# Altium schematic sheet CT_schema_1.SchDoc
size 526 x 485 mm
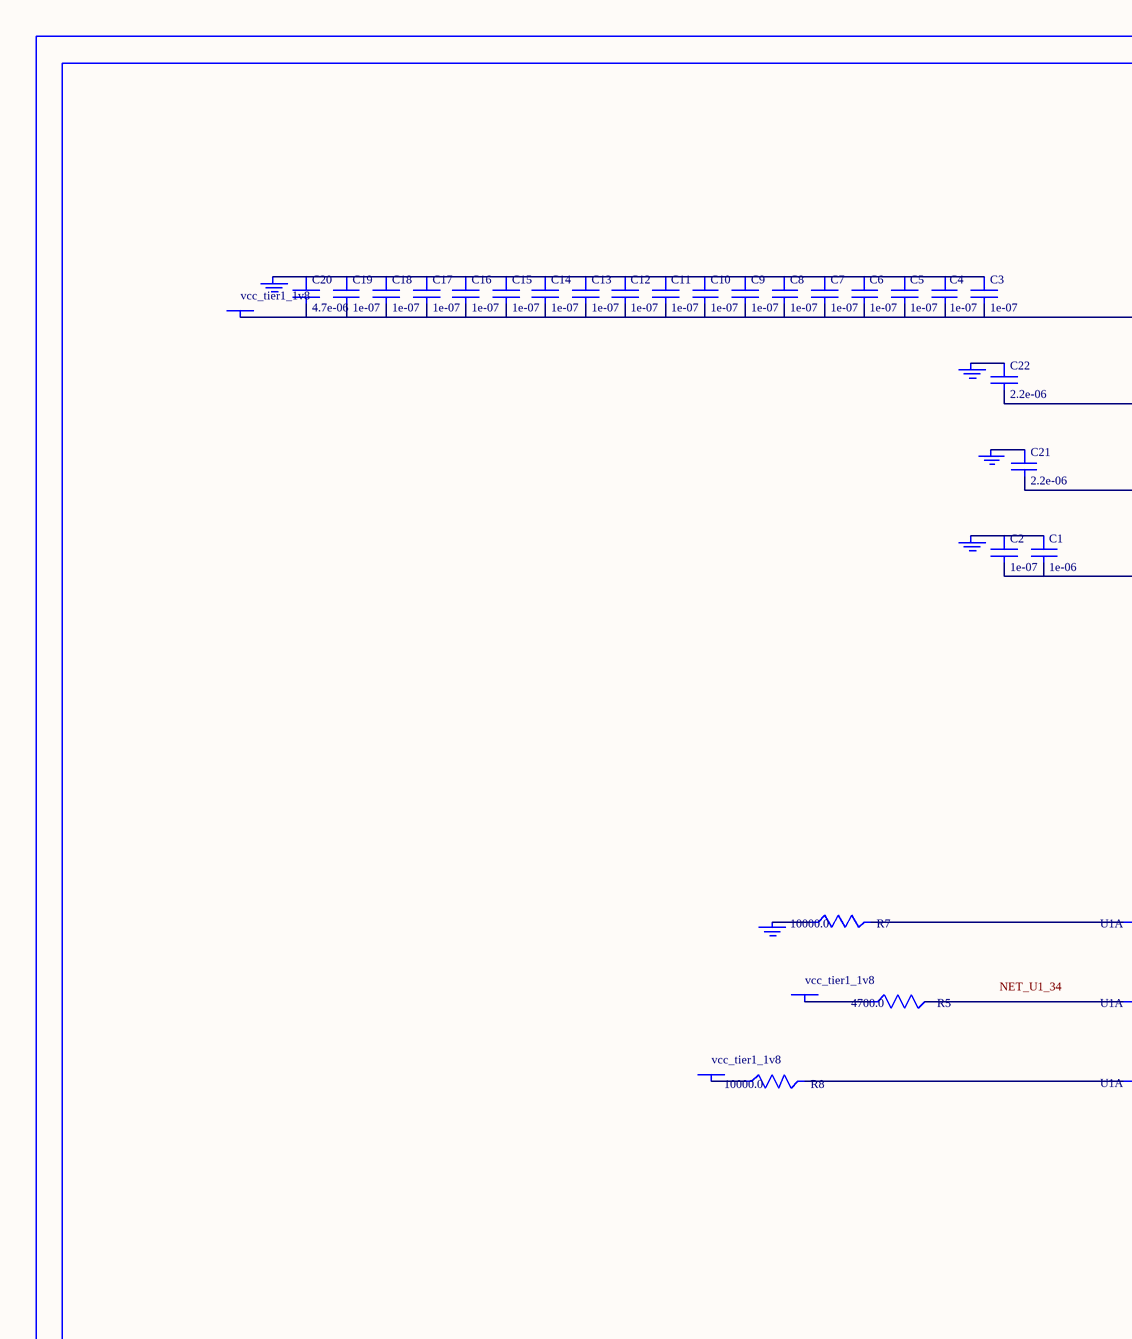
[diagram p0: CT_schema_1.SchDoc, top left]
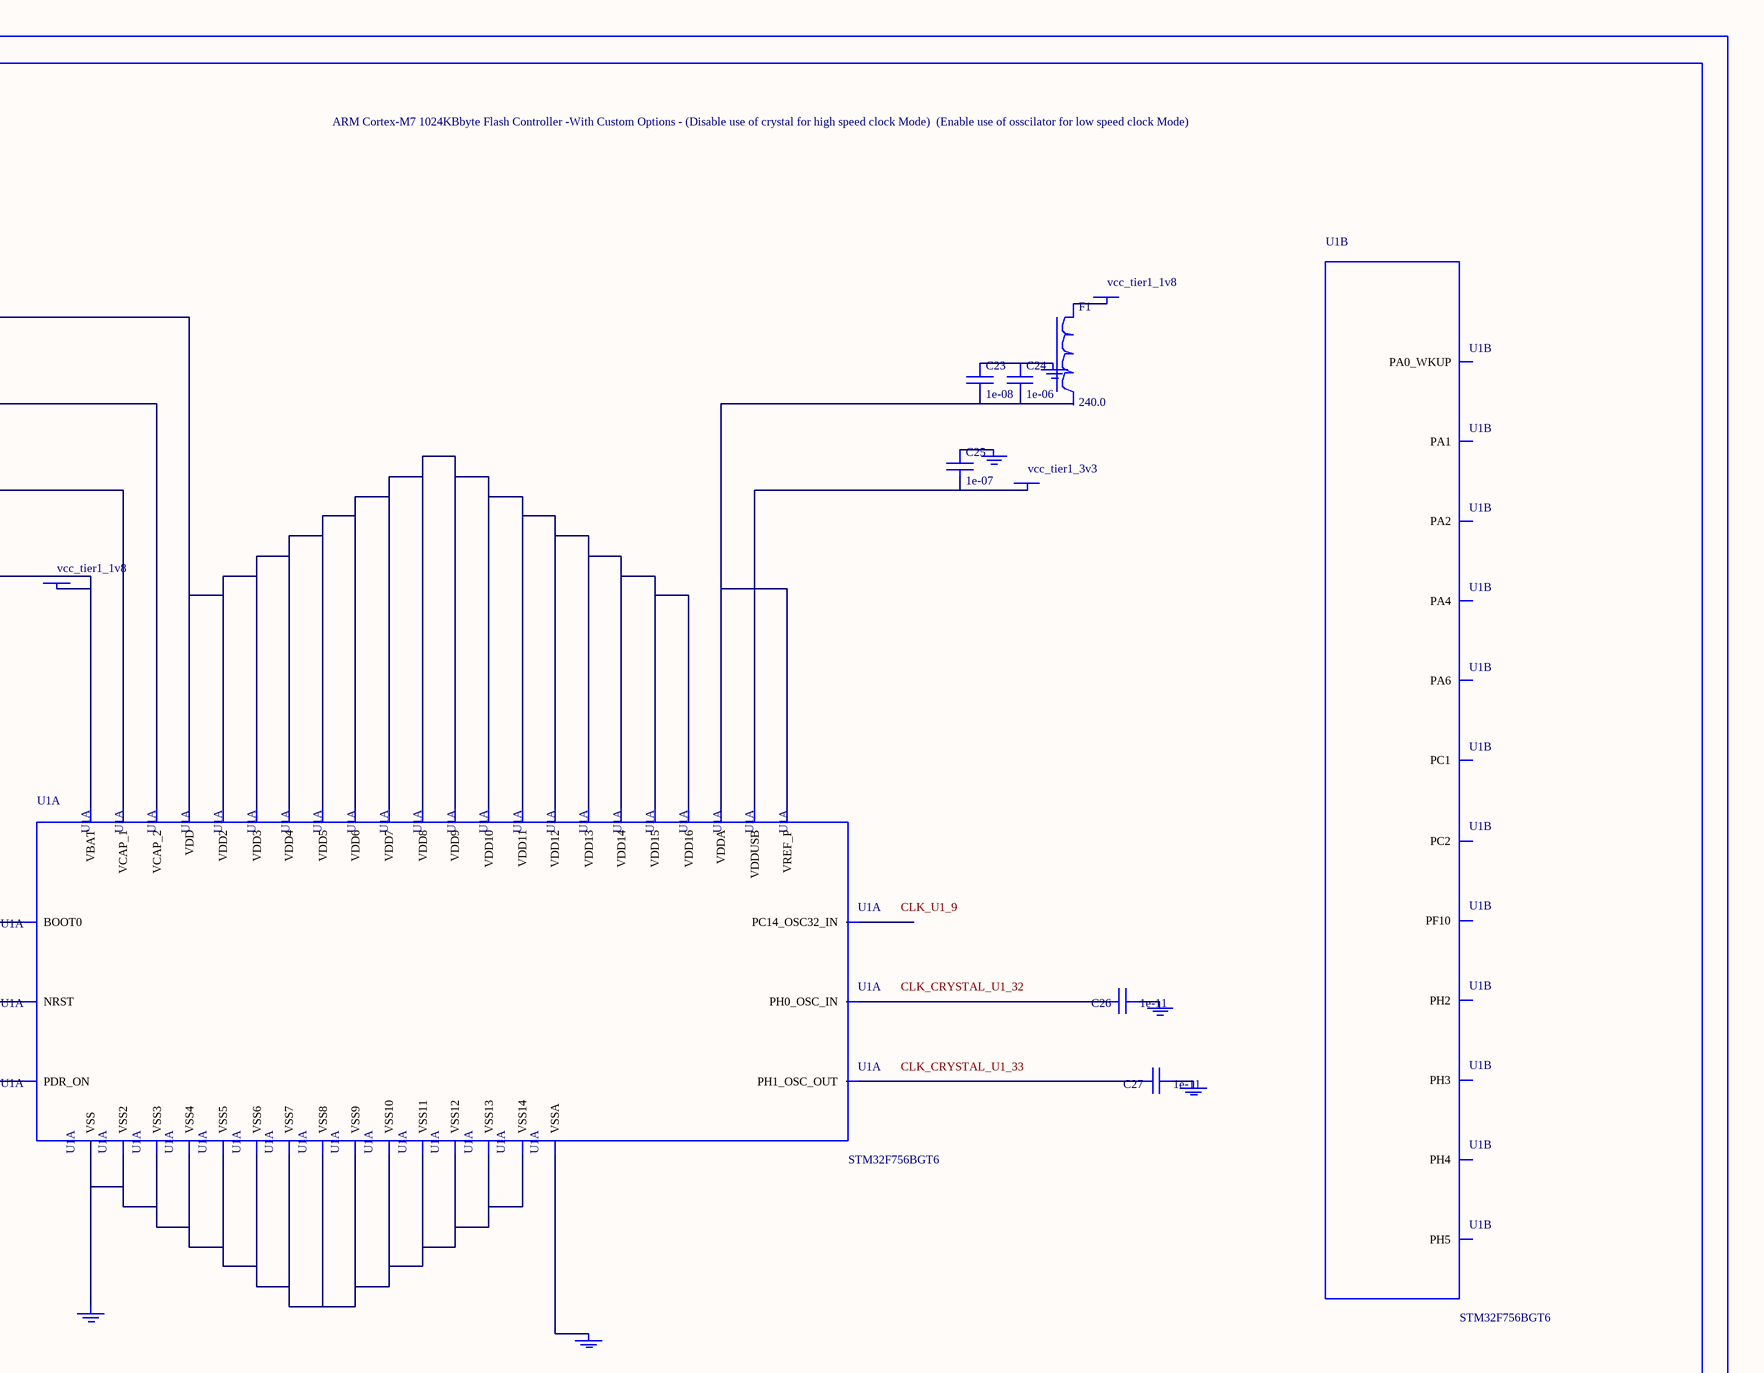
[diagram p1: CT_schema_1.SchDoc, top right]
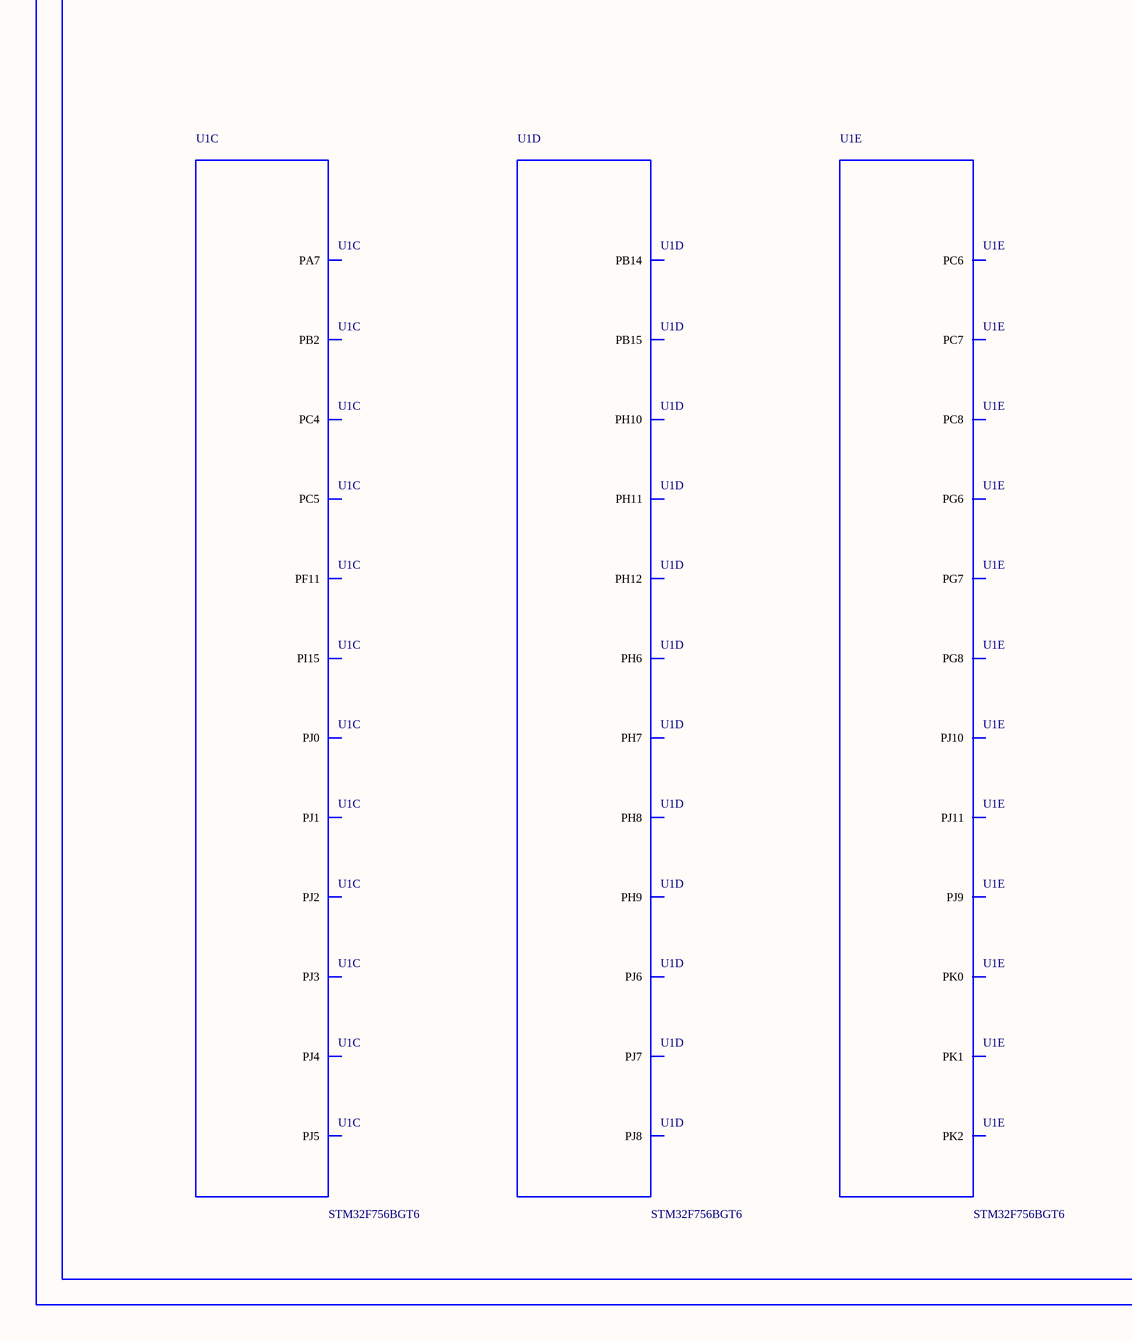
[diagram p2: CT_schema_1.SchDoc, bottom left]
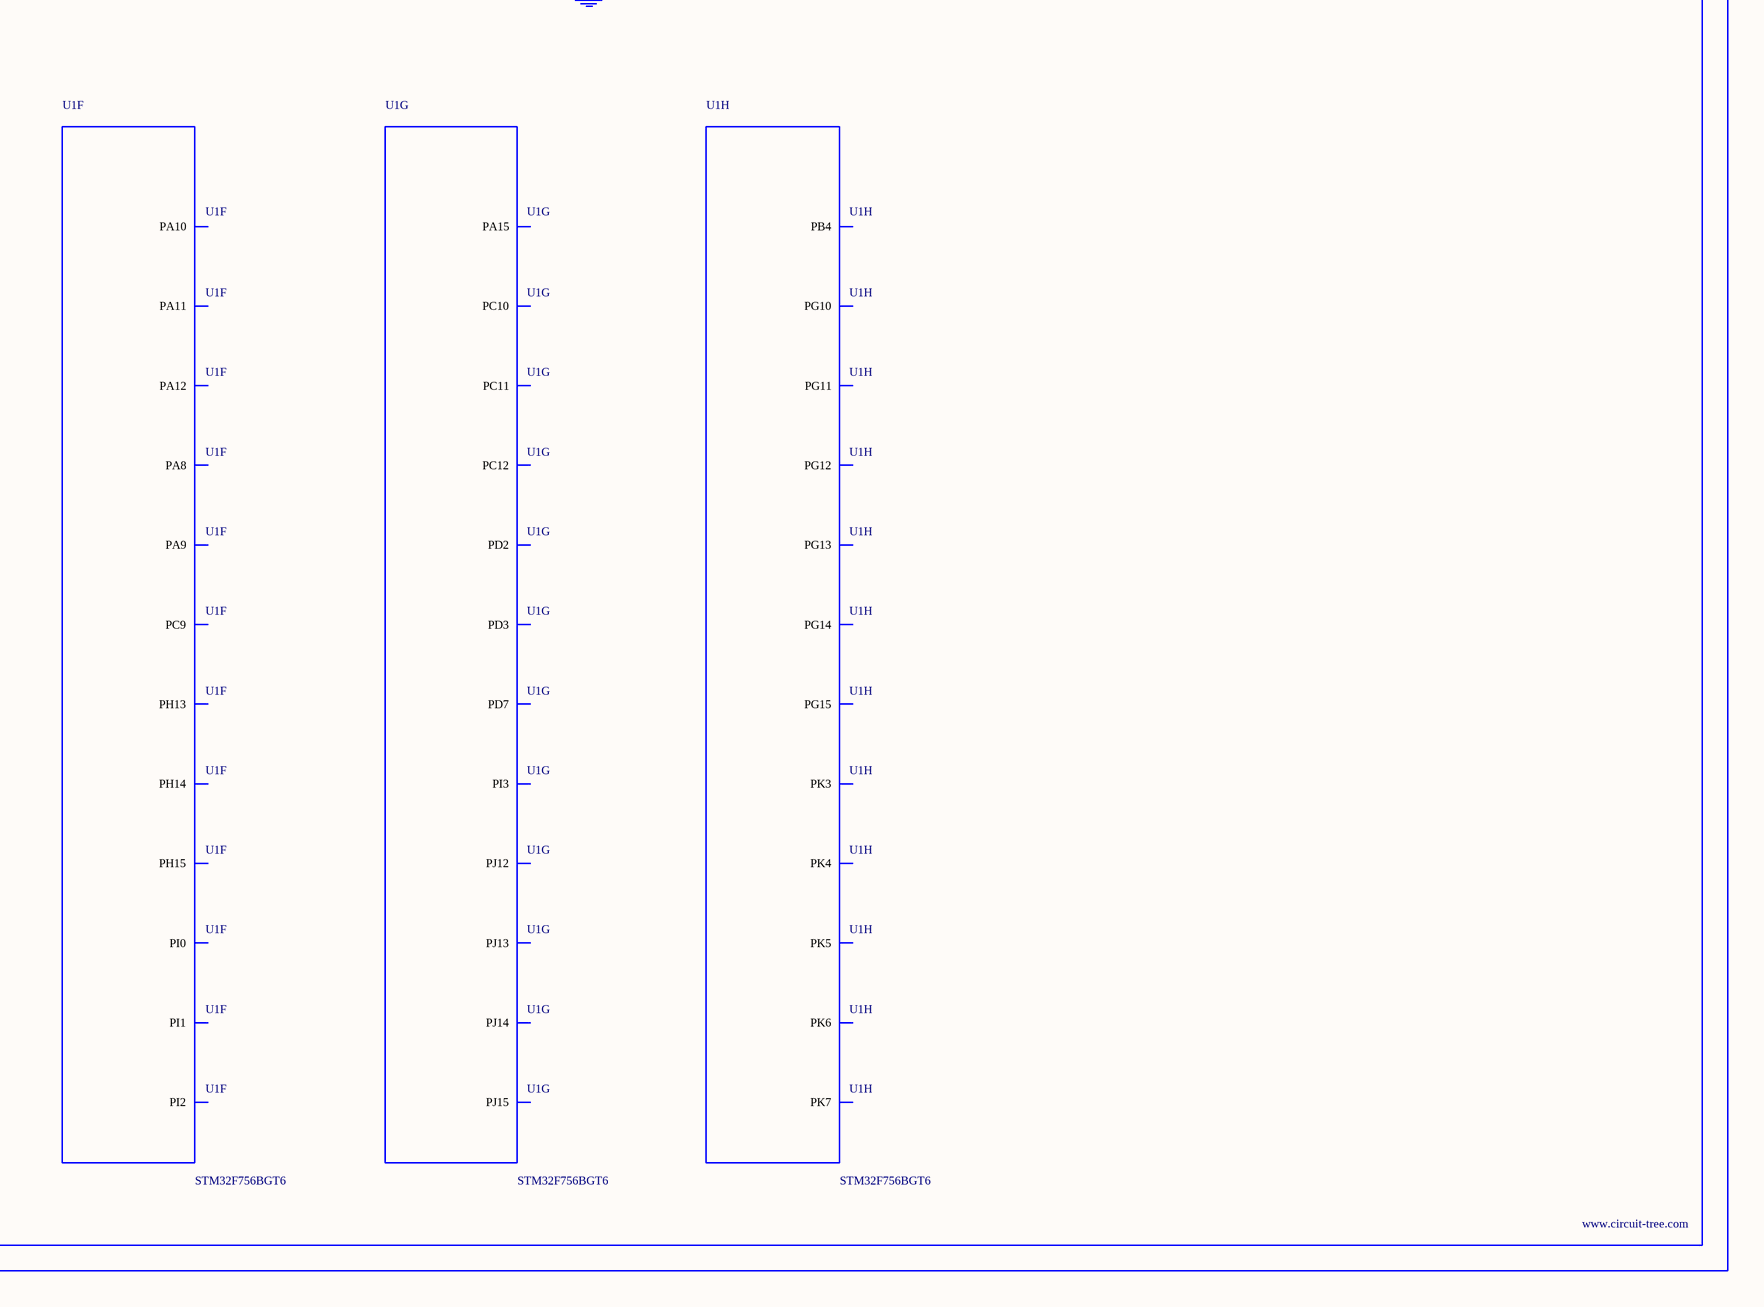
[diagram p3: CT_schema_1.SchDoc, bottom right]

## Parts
BORDER0  (no value)
C1  1e-06  [C0603]
C2  1e-07  [C0603]
C3  1e-07  [C0603]
C4  1e-07  [C0603]
C5  1e-07  [C0603]
C6  1e-07  [C0603]
C7  1e-07  [C0603]
C8  1e-07  [C0603]
C9  1e-07  [C0603]
C10  1e-07  [C0603]
C11  1e-07  [C0603]
C12  1e-07  [C0603]
C13  1e-07  [C0603]
C14  1e-07  [C0603]
C15  1e-07  [C0603]
C16  1e-07  [C0603]
C17  1e-07  [C0603]
C18  1e-07  [C0603]
C19  1e-07  [C0603]
C20  4.7e-06  [C0603]
C21  2.2e-06  [C0603]
C22  2.2e-06  [C0603]
C23  1e-08  [C0603]
C24  1e-06  [C0603]
C25  1e-07  [C0603]
C26  1e-11  [C0402]
C27  1e-11  [C0402]
F1  240.0  [L0603]
GND_INSTANCE_0_0  (no value)
GND_INSTANCE_0_1  (no value)
GND_INSTANCE_0_2  (no value)
GND_INSTANCE_0_3  (no value)
GND_INSTANCE_0_4  (no value)
GND_INSTANCE_0_5  (no value)
GND_INSTANCE_0_6  (no value)
GND_INSTANCE_0_7  (no value)
GND_INSTANCE_0_8  (no value)
GND_INSTANCE_0_9  (no value)
GND_INSTANCE_0_10  (no value)
POWER_INSTANCE_0_0  vcc_tier1_1v8
POWER_INSTANCE_0_1  vcc_tier1_1v8
POWER_INSTANCE_0_2  vcc_tier1_1v8
POWER_INSTANCE_0_3  vcc_tier1_3v3
POWER_INSTANCE_0_4  vcc_tier1_1v8
POWER_INSTANCE_0_5  vcc_tier1_1v8
R5  4700.0  [R0603]
R7  10000.0  [R0603]
R8  10000.0  [R0603]
U1  STM32F756BGT6  [LQFP208]  (parts A,B,C,D,E,F,G,H of 15)

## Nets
NetC1_1: C1.1 C2.1 GND_INSTANCE_0_0.0(GND)
NetC1_2: C1.2 C2.2 POWER_INSTANCE_0_0.0(PWR) U1.6(VBAT)
NetC3_1: C3.1 C4.1 C5.1 C6.1 C7.1 C8.1 C9.1 C10.1 C11.1 C12.1 C13.1 C14.1 C15.1 C16.1 C17.1 C18.1 C19.1 C20.1 GND_INSTANCE_0_1.0(GND)
NetC3_2: C3.2 C4.2 C5.2 C6.2 C7.2 C8.2 C9.2 C10.2 C11.2 C12.2 C13.2 C14.2 C15.2 C16.2 C17.2 C18.2 C19.2 C20.2 POWER_INSTANCE_0_1.0(PWR) U1.15(VDD) U1.26(VDD2) U1.39(VDD3) U1.52(VDD4) U1.59(VDD5) U1.73(VDD6) U1.83(VDD7) U1.94(VDD8) U1.103(VDD9) U1.115(VDD10) U1.124(VDD11) U1.150(VDD12) U1.158(VDD13) U1.171(VDD14) U1.185(VDD15) U1.204(VDD16)
NetC21_1: C21.1 GND_INSTANCE_0_6.0(GND)
NetC21_2: C21.2 U1.92(VCAP_1)
NetC22_1: C22.1 GND_INSTANCE_0_8.0(GND)
NetC22_2: C22.2 U1.148(VCAP_2)
NetC23_1: C23.1 C24.1 GND_INSTANCE_0_5.0(GND)
NetC23_2: C23.2 C24.2 U1.41(VREF_P) U1.42(VDDA)
NetC25_1: C25.1 GND_INSTANCE_0_7.0(GND)
NetC25_2: C25.2 POWER_INSTANCE_0_3.0(PWR) U1.137(VDDUSB)
NetC26_1: C26.1 GND_INSTANCE_0_2.0(GND)
NetC26_2: C26.2 U1.32(PH0_OSC_IN)
NetC27_1: C27.1 GND_INSTANCE_0_3.0(GND)
NetC27_2: C27.2 U1.33(PH1_OSC_OUT)
NetF1_1: F1.1 POWER_INSTANCE_0_2.0(PWR)
NetGND_INSTANCE_0_4_0: GND_INSTANCE_0_4.0(GND) U1.40(VSSA)
NetGND_INSTANCE_0_9_0: GND_INSTANCE_0_9.0(GND) R7.1
NetGND_INSTANCE_0_10_0: GND_INSTANCE_0_10.0(GND) U1.14(VSS) U1.25(VSS2) U1.51(VSS3) U1.60(VSS4) U1.72(VSS5) U1.82(VSS6) U1.93(VSS7) U1.114(VSS8) U1.125(VSS9) U1.136(VSS10) U1.149(VSS11) U1.170(VSS12) U1.184(VSS13) U1.202(VSS14)
NetPOWER_INSTANCE_0_4_0: POWER_INSTANCE_0_4.0(PWR) R8.1
NetPOWER_INSTANCE_0_5_0: POWER_INSTANCE_0_5.0(PWR) R5.1
NetR5_2: R5.2 U1.34(NRST)
NetR7_2: R7.2 U1.197(BOOT0)
NetR8_2: R8.2 U1.203(PDR_ON)

Not connected (* = marked no-connect by the designer): F1 2; U1 9(PC14_OSC32_IN) 31(PF10) 36(PC1) 37(PC2) 43(PA0_WKUP) 44(PA1) 45(PA2) 46(PH2) 47(PH3) 48(PH4) 49(PH5) 53(PA4) 55(PA6) 56(PA7) 57(PC4) 58(PC5) 63(PB2) 64(PI15) 65(PJ0) 66(PJ1) 67(PJ2) 68(PJ3) 69(PJ4) 70(PF11) 95(PJ5) 96(PH6) 97(PH7) 98(PH8) 99(PH9) 100(PH10) 101(PH11) 102(PH12) 106(PB14) 107(PB15) 118(PJ6) 119(PJ7) 120(PJ8) 121(PJ9) 122(PJ10) 123(PJ11) 126(PK0) 127(PK1) 128(PK2) 133(PG6) 134(PG7) 135(PG8) 138(PC6) 139(PC7) 140(PC8) 141(PC9) 142(PA8) 143(PA9) 144(PA10) 145(PA11) 146(PA12) 151(PH13) 152(PH14) 153(PH15) 154(PI0) 155(PI1) 156(PI2) 157(PI3) 160(PA15) 161(PC10) 162(PC11) 163(PC12) 166(PD2) 167(PD3) 173(PD7) 174(PJ12) 175(PJ13) 176(PJ14) 177(PJ15) 179(PG10) 180(PG11) 181(PG12) 182(PG13) 183(PG14) 186(PK3) 187(PK4) 188(PK5) 189(PK6) 190(PK7) 191(PG15) 193(PB4)

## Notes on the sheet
- Labels drawn without touching a wire or pin: CLK_CRYSTAL_U1_32, CLK_CRYSTAL_U1_33, CLK_U1_9, NET_U1_34

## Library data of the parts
BORDER0 = BORDER_PAGE0
C1 C24 = C0603C105K3RACTU
C2-C19 C25 = 06035C104K4Z2A
C20 = GRM188R6YA475KE15D
C21 C22 = C0603C225K8RACTU
C23 = 06035C103K4Z2A
C26 C27 = C0402C100K3GACTU
F1 = Z0603C241ASMST
GND_INSTANCE_0_0-GND_INSTANCE_0_10 = GND
POWER_INSTANCE_0_0-POWER_INSTANCE_0_5 = PWR
R5 = RC0603JR-074K7L
R7 R8 = RC0603JR-0710KL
